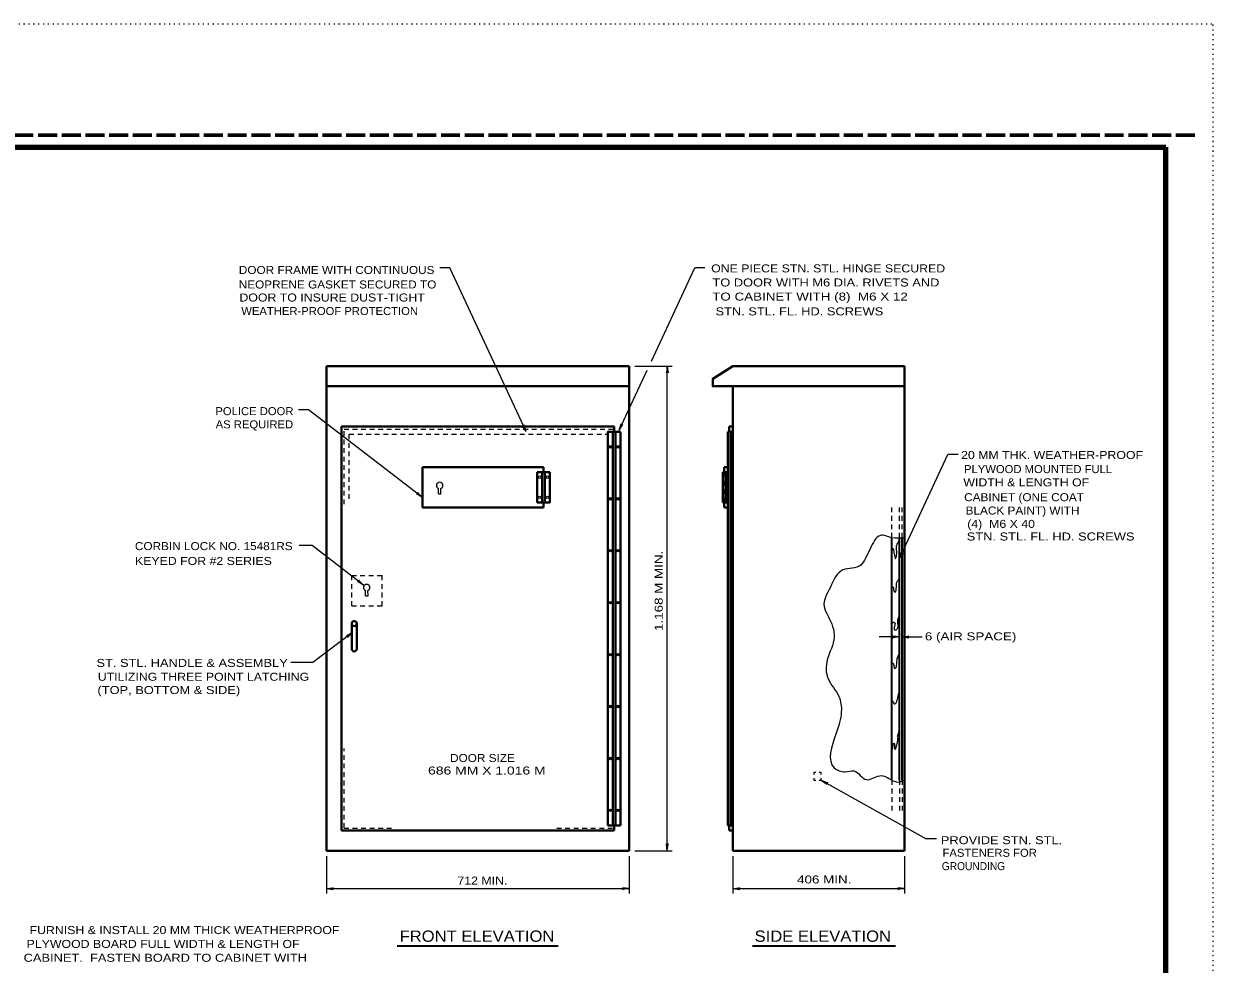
# Model space of a CAD drawing. Extents: x 312583 to 312854, y 144419 to 144597.
# Drawn here: x 312740.6 to 312853.5, y 144507.5 to 144596.8 of the extents above; entities that cross this region are included whole.
import ezdxf
from ezdxf.enums import TextEntityAlignment as Align

# ---------------------------------------------------------------- set-up
doc = ezdxf.new("R2010")
doc.units = 0
doc.header["$LTSCALE"] = 0.3
doc.header["$PDMODE"] = 32
doc.header["$PDSIZE"] = 0.15
for name, pattern in [('DOTTED', [1.5, 0.3, -1.2]), ('LONG_DASHED', [7.5, 6, -1.5]), ('SHORT_DASHED', [2.7, 1.5, -1.2])]:
    doc.linetypes.add(name, pattern=pattern)
for name, color, linetype, lineweight in [('1', 7, 'Continuous', 25), ('2', 7, 'Continuous', 13), ('63', 7, 'DOTTED', 13)]:
    doc.layers.add(name, color=color, linetype=linetype, lineweight=lineweight)

msp = doc.modelspace()

# ---------------------------------------------------------------- linework, layer by layer
at = {"layer": '1', "linetype": 'LONG_DASHED', "lineweight": 60}
msp.add_line((312851.75, 144586.2246), (312583.526, 144586.2246), dxfattribs=at)
at = {"layer": '1', "lineweight": 158}
msp.add_line((312849, 144423.1446), (312849, 144585.0846), dxfattribs=at)
at = {"layer": '1', "lineweight": 106}
msp.add_line((312849, 144423.1446), (312849, 144584.0756), dxfattribs=at)
at = {"layer": '1', "lineweight": 40}
for p, q in [((312769.3243, 144518.2993), (312769.3243, 144564.2993)), ((312769.3243, 144564.2993), (312798.0743, 144564.2993)), ((312798.0743, 144564.2993), (312798.0743, 144518.2993)), ((312824.2023, 144564.2993), (312807.9107, 144564.2993)), ((312824.2023, 144564.2993), (312824.2023, 144518.2993)), ((312769.3243, 144562.3827), (312798.0743, 144562.3827)), ((312807.9107, 144562.3827), (312807.9107, 144518.2993)), ((312796.518, 144520.6913), (312796.518, 144558.0663)), ((312796.6407, 144558.0663), (312796.6407, 144558.5493)), ((312796.7633, 144520.6913), (312796.7633, 144558.0663)), ((312797.2387, 144520.6913), (312797.2387, 144558.0663)), ((312807.4353, 144558.0663), (312807.4353, 144520.6913)), ((312807.9107, 144558.0663), (312807.4353, 144558.0663)), ((312807.9107, 144558.5493), (312807.5503, 144558.5493)), ((312807.5503, 144558.0663), (312807.5503, 144558.5493)), ((312807.673, 144558.0663), (312807.673, 144520.6913)), ((312778.4323, 144554.716), (312789.9323, 144554.716)), ((312778.4323, 144550.8827), (312778.4323, 144554.716)), ((312789.9323, 144554.233), (312789.9323, 144554.716)), ((312807.4353, 144554.716), (312807.075, 144554.716)), ((312807.075, 144554.716), (312807.075, 144554.233)), ((312789.3343, 144554.233), (312790.5303, 144554.233)), ((312789.3343, 144551.358), (312789.3343, 144554.233)), ((312789.8097, 144551.358), (312789.8097, 144554.233)), ((312790.055, 144551.358), (312790.055, 144554.233)), ((312806.9523, 144554.233), (312806.9523, 144551.358)), ((312806.9523, 144554.233), (312807.4353, 144554.233)), ((312807.1977, 144554.233), (312807.1977, 144551.358)), ((312789.9323, 144550.8827), (312789.9323, 144551.358)), ((312806.9523, 144551.358), (312807.4353, 144551.358)), ((312807.075, 144551.358), (312807.075, 144550.8827)), ((312778.4323, 144550.8827), (312789.9323, 144550.8827)), ((312807.4353, 144550.8827), (312807.075, 144550.8827)), ((312771.724, 144537.466), (312771.724, 144539.858)), ((312772.1993, 144537.466), (312772.1993, 144539.858)), ((312796.0427, 144520.6913), (312797.2387, 144520.6913)), ((312796.6407, 144520.216), (312796.6407, 144520.6913)), ((312807.4353, 144520.6913), (312807.9107, 144520.6913)), ((312807.5503, 144520.216), (312807.5503, 144520.6913)), ((312770.7657, 144520.216), (312796.6407, 144520.216)), ((312807.5503, 144520.216), (312807.9107, 144520.216)), ((312769.3243, 144518.2993), (312798.0743, 144518.2993)), ((312807.9107, 144518.2993), (312824.2023, 144518.2993))]:
    msp.add_line(p, q, dxfattribs=at)
at = {"layer": '1', "linetype": 'SHORT_DASHED'}
for p, q in [((312771.0033, 144558.3117), (312796.518, 144558.3117)), ((312771.0033, 144551.197), (312771.0033, 144558.3117)), ((312771.4863, 144557.8287), (312796.0427, 144557.8287)), ((312771.4863, 144551.6877), (312771.4863, 144557.8287)), ((312807.075, 144554.233), (312807.075, 144551.358)), ((312823.0063, 144548.0077), (312823.0063, 144550.8827)), ((312823.727, 144548.0077), (312823.727, 144550.8827)), ((312823.9647, 144548.0077), (312823.9647, 144550.8827)), ((312771.0033, 144520.4537), (312771.0033, 144528.0207)), ((312823.0063, 144525.0077), (312823.0063, 144522.1327)), ((312823.727, 144525.0077), (312823.727, 144522.1327)), ((312823.9647, 144525.0077), (312823.9647, 144522.1327)), ((312771.0033, 144520.4537), (312775.588, 144520.4537)), ((312791.182, 144520.4537), (312796.518, 144520.4537))]:
    msp.add_line(p, q, dxfattribs=at)
at = {"layer": '1'}
for p, q in [((312779.958, 144552.163), (312779.9657, 144552.6767)), ((312780.1957, 144552.163), (312780.188, 144552.6767)), ((312779.958, 144552.163), (312780.1957, 144552.163)), ((312773.0273, 144542.48), (312773.035, 144542.9937)), ((312773.0273, 144542.48), (312773.2727, 144542.48)), ((312773.2727, 144542.48), (312773.265, 144542.9937)), ((312816.298, 144525.7283), (312816.1063, 144525.7283)), ((312816.298, 144525.529), (312816.298, 144525.7283))]:
    msp.add_line(p, q, dxfattribs=at)
at = {"layer": '1', "lineweight": 35}
for p, q in [((312823.0063, 144525.0077), (312823.0063, 144548.0077)), ((312823.727, 144525.0077), (312823.727, 144548.0077)), ((312823.9647, 144525.0077), (312823.9647, 144548.0077))]:
    msp.add_line(p, q, dxfattribs=at)
at = {"layer": '1', "lineweight": 158}
msp.add_lwpolyline([(312616.5, 144423.1446), (312616.5, 144585.0846), (312849, 144585.0846)], dxfattribs=at)
at = {"layer": '1', "lineweight": 40}
for points in [[(312824.2023, 144562.3827), (312805.994, 144562.3827), (312805.994, 144563.1033), (312807.9107, 144564.2993)], [(312770.7657, 144520.216), (312770.7657, 144558.5493), (312796.6407, 144558.5493)], [(312796.0427, 144520.6913), (312796.0427, 144558.0663), (312797.2387, 144558.0663)], [(312789.3343, 144551.358), (312790.5303, 144551.358), (312790.5303, 144554.233)]]:
    msp.add_lwpolyline(points, dxfattribs=at)
at = {"layer": '1', "linetype": 'SHORT_DASHED'}
for points in [[(312771.724, 144541.537), (312771.724, 144544.412), (312774.599, 144544.412)], [(312771.724, 144541.537), (312774.599, 144541.537), (312774.599, 144544.412)]]:
    msp.add_lwpolyline(points, dxfattribs=at)
at = {"layer": '1'}
for points in [[(312815.7767, 144525.7283), (312815.5773, 144525.7283), (312815.5773, 144525.529)], [(312815.5773, 144525.1993), (312815.5773, 144525.0077), (312815.769, 144525.0077)], [(312816.1063, 144525.0077), (312816.298, 144525.0077), (312816.298, 144525.1993)]]:
    msp.add_lwpolyline(points, dxfattribs=at)
for centre in [(312796.2803, 144556.6308), (312796.9991, 144556.6308), (312789.572, 144553.7567), (312790.2907, 144553.7567), (312789.572, 144551.84), (312790.2907, 144551.84), (312796.2803, 144551.703), (312796.9991, 144551.703), (312796.2803, 144546.7743), (312796.9991, 144546.7743), (312796.2803, 144541.8456), (312796.9991, 144541.8456), (312796.2803, 144536.9169), (312796.9991, 144536.9169), (312796.2803, 144531.9882), (312796.9991, 144531.9882), (312796.2803, 144527.0595), (312796.9991, 144527.0595), (312796.2803, 144522.1317), (312796.9991, 144522.1317)]:
    msp.add_circle(centre, 0.1198, dxfattribs=at)
at = {"layer": '1', "lineweight": 40}
msp.add_circle((312771.9626, 144539.8609), 0.2396, dxfattribs=at)
at = {"layer": '1'}
for centre in [(312780.0768, 144552.9632), (312773.149, 144543.2773)]:
    msp.add_arc(centre, 0.3047, 291.97661, 248.03135, dxfattribs=at)
at = {"layer": '1', "lineweight": 40}
msp.add_arc((312771.9626, 144537.465), 0.2396, 180, 0, dxfattribs=at)
at = {"layer": '1'}
msp.add_spline([(312824.2023, 144548.0077), (312823.0063, 144548.0077), (312821.91, 144548.23), (312820.944, 144546.965), (312820.4993, 144546.0757), (312820.0547, 144545.4087), (312818.345, 144544.9563), (312817.1567, 144543.3233), (312816.5663, 144541.468), (312816.9343, 144540.5787), (312817.5323, 144538.57), (312816.8653, 144536.4157), (312816.9343, 144534.637), (312817.977, 144532.9273), (312818.1993, 144531.5167), (312817.678, 144529.3623), (312817.5323, 144526.1653), (312818.5673, 144525.7973), (312819.3877, 144525.874), (312820.576, 144525.0537), (312821.841, 144525.4217), (312823.0063, 144525.0077), (312823.3973, 144524.8313), (312824.2023, 144525.0077)], degree=3, dxfattribs=at)
at = {"layer": '1', "lineweight": 13}
for points in [[(312823.014, 144546.6583), (312823.0447, 144546.827), (312823.129, 144546.988), (312823.1673, 144546.873), (312823.198, 144546.6047), (312823.2823, 144546.183), (312823.3207, 144546.022), (312823.451, 144546.3287), (312823.4663, 144546.7197), (312823.428, 144547.1567), (312823.5507, 144547.4863), (312823.704, 144547.793)], [(312822.9987, 144543.1853), (312823.0447, 144543.3233), (312823.083, 144543.3463), (312823.152, 144543.285), (312823.152, 144543.1087), (312823.2287, 144542.917), (312823.2747, 144542.848), (312823.4203, 144543.1547), (312823.428, 144543.377), (312823.4433, 144543.6683), (312823.543, 144543.906), (312823.635, 144544.0133), (312823.727, 144544.228)], [(312822.9833, 144539.697), (312823.06, 144539.8887), (312823.1213, 144540.019), (312823.267, 144539.9423), (312823.2363, 144539.5973), (312823.3053, 144539.2293), (312823.497, 144539.3673), (312823.5813, 144539.812), (312823.5583, 144540.2183), (312823.6963, 144540.5633)], [(312823.014, 144535.9403), (312823.0523, 144536.0783), (312823.0677, 144536.109), (312823.1597, 144536.017), (312823.198, 144535.8407), (312823.221, 144535.672), (312823.2747, 144535.5877), (312823.3973, 144535.7027), (312823.451, 144535.8637), (312823.474, 144536.1703), (312823.4893, 144536.4233), (312823.5507, 144536.6457), (312823.6043, 144536.7683), (312823.6963, 144537.1133)], [(312823.014, 144532.429), (312823.0217, 144532.475), (312823.06, 144532.5057), (312823.1213, 144532.452), (312823.1597, 144532.3523), (312823.2287, 144532.2373), (312823.3513, 144532.2757), (312823.4587, 144532.4903), (312823.52, 144532.705), (312823.5737, 144532.8813), (312823.6197, 144533.142), (312823.6733, 144533.303), (312823.727, 144533.418)], [(312823.0063, 144527.7753), (312823.0293, 144527.875), (312823.0677, 144528.0207), (312823.0907, 144528.1203), (312823.106, 144528.289), (312823.1597, 144528.473), (312823.198, 144528.5037), (312823.2363, 144528.4347), (312823.244, 144528.2507), (312823.244, 144528.1203), (312823.2593, 144528.0053), (312823.2977, 144527.944), (312823.3207, 144527.9287), (312823.359, 144527.967), (312823.3973, 144528.0667), (312823.4357, 144528.2507), (312823.5047, 144528.473), (312823.566, 144528.8717), (312823.5813, 144529.0403), (312823.566, 144529.232), (312823.6197, 144529.4467), (312823.704, 144529.7687)]]:
    msp.add_spline(points, degree=3, dxfattribs=at)
at = {"layer": '1'}
for p in [(312796.2803, 144556.6327), (312797.001, 144556.6327), (312796.2803, 144551.703), (312797.001, 144551.703), (312796.2803, 144546.7733), (312797.001, 144546.7733), (312796.2803, 144541.8437), (312797.001, 144541.8437), (312796.2803, 144536.914), (312797.001, 144536.914), (312796.2803, 144531.9843), (312797.001, 144531.9843), (312796.2803, 144527.0623), (312797.001, 144527.0623), (312796.2803, 144522.1327), (312797.001, 144522.1327)]:
    msp.add_point(p, dxfattribs=at)
at = {"layer": '2'}
for p, q in [((312800.1673, 144564.767), (312804.2843, 144573.6143)), ((312805.2427, 144573.6143), (312804.2843, 144573.6143)), ((312797.1083, 144558.2043), (312799.761, 144563.9007)), ((312798.6033, 144564.2993), (312802.153, 144564.2993)), ((312801.67, 144564.2993), (312801.5933, 144563.6477)), ((312801.5933, 144563.6477), (312801.67, 144563.8547)), ((312801.67, 144518.2993), (312801.67, 144564.2993)), ((312801.67, 144564.2993), (312801.7543, 144563.6477)), ((312801.7543, 144563.6477), (312801.67, 144563.8547)), ((312767.63, 144560.1517), (312766.664, 144560.1517)), ((312778.4323, 144551.841), (312767.63, 144560.1517)), ((312787.9237, 144558.6413), (312788.0847, 144558.488)), ((312788.2763, 144558.0893), (312787.9237, 144558.6413)), ((312788.0693, 144558.7103), (312788.0847, 144558.488)), ((312788.2763, 144558.0893), (312788.0693, 144558.7103)), ((312797.1083, 144558.2043), (312797.3153, 144558.833)), ((312797.1083, 144558.2043), (312797.461, 144558.764)), ((312797.3153, 144558.833), (312797.3, 144558.6107)), ((312797.461, 144558.764), (312797.3, 144558.6107)), ((312823.727, 144546.022), (312828.3193, 144555.8967)), ((312829.2777, 144555.8967), (312828.3193, 144555.8967)), ((312777.9647, 144552.301), (312778.0797, 144552.1093)), ((312778.4323, 144551.841), (312777.9647, 144552.301)), ((312777.865, 144552.1707), (312778.0797, 144552.1093)), ((312778.4323, 144551.841), (312777.865, 144552.1707)), ((312767.9673, 144547.264), (312766.7483, 144547.264)), ((312772.8357, 144543.515), (312767.9673, 144547.264)), ((312823.727, 144546.022), (312823.9263, 144546.643)), ((312823.9263, 144546.643), (312823.911, 144546.4207)), ((312823.727, 144546.022), (312824.072, 144546.574)), ((312824.072, 144546.574), (312823.911, 144546.4207)), ((312772.2683, 144543.8523), (312772.483, 144543.791)), ((312772.8357, 144543.515), (312772.2683, 144543.8523)), ((312772.368, 144543.975), (312772.483, 144543.791)), ((312772.8357, 144543.515), (312772.368, 144543.975)), ((312771.793, 144539.007), (312768.0363, 144536.1627)), ((312771.793, 144539.007), (312771.2257, 144538.6773)), ((312771.2257, 144538.6773), (312771.4403, 144538.7387)), ((312771.793, 144539.007), (312771.3253, 144538.5547)), ((312771.3253, 144538.5547), (312771.4403, 144538.7387)), ((312823.727, 144538.593), (312821.8027, 144538.593)), ((312823.0753, 144538.6697), (312823.2823, 144538.593)), ((312823.727, 144538.593), (312823.0753, 144538.6697)), ((312823.0753, 144538.5087), (312823.2823, 144538.593)), ((312823.727, 144538.593), (312823.0753, 144538.5087)), ((312823.9647, 144538.593), (312824.6163, 144538.6697)), ((312823.9647, 144538.593), (312825.8813, 144538.593)), ((312823.9647, 144538.593), (312824.6163, 144538.5087)), ((312824.6163, 144538.6697), (312824.4093, 144538.593)), ((312824.6163, 144538.5087), (312824.4093, 144538.593)), ((312768.0363, 144536.1627), (312765.9587, 144536.1627)), ((312816.298, 144525.0077), (312826.2647, 144519.4187)), ((312816.298, 144525.0077), (312816.827, 144524.6167)), ((312816.298, 144525.0077), (312816.9037, 144524.7623)), ((312816.827, 144524.6167), (312816.6813, 144524.793)), ((312816.9037, 144524.7623), (312816.6813, 144524.793)), ((312801.5933, 144518.951), (312801.67, 144518.744)), ((312801.67, 144518.2993), (312801.5933, 144518.951)), ((312801.7543, 144518.951), (312801.67, 144518.744)), ((312801.67, 144518.2993), (312801.7543, 144518.951)), ((312827.223, 144519.4187), (312826.2647, 144519.4187)), ((312769.3243, 144517.778), (312769.3243, 144514.2283)), ((312798.0743, 144517.778), (312798.0743, 144514.2283)), ((312798.6033, 144518.2993), (312802.153, 144518.2993)), ((312807.9107, 144517.778), (312807.9107, 144514.2283)), ((312824.2023, 144517.778), (312824.2023, 144514.2283)), ((312769.3243, 144514.7037), (312769.976, 144514.788)), ((312769.3243, 144514.7037), (312798.0743, 144514.7037)), ((312769.3243, 144514.7037), (312769.976, 144514.627)), ((312769.976, 144514.788), (312769.769, 144514.7037)), ((312769.976, 144514.627), (312769.769, 144514.7037)), ((312797.4303, 144514.788), (312797.6373, 144514.7037)), ((312798.0743, 144514.7037), (312797.4303, 144514.788)), ((312797.4303, 144514.627), (312797.6373, 144514.7037)), ((312798.0743, 144514.7037), (312797.4303, 144514.627)), ((312807.9107, 144514.7037), (312808.5623, 144514.788)), ((312807.9107, 144514.7037), (312824.2023, 144514.7037)), ((312807.9107, 144514.7037), (312808.5623, 144514.627)), ((312808.5623, 144514.788), (312808.3553, 144514.7037)), ((312808.5623, 144514.627), (312808.3553, 144514.7037)), ((312823.5583, 144514.788), (312823.7653, 144514.7037)), ((312824.2023, 144514.7037), (312823.5583, 144514.788)), ((312823.5583, 144514.627), (312823.7653, 144514.7037)), ((312824.2023, 144514.7037), (312823.5583, 144514.627))]:
    msp.add_line(p, q, dxfattribs=at)
at = {"layer": '2', "lineweight": 35}
for p, q in [((312776.0474, 144509.2833), (312791.3211, 144509.2833)), ((312809.7603, 144509.2833), (312823.3524, 144509.2833))]:
    msp.add_line(p, q, dxfattribs=at)
at = {"layer": '2'}
msp.add_lwpolyline([(312788.2763, 144558.0893), (312781.0467, 144573.6143), (312780.0883, 144573.6143)], dxfattribs=at)
at = {"layer": '63'}
msp.add_line((312601.2, 144596.7846), (312853.5, 144596.7846), dxfattribs=at)
msp.add_lwpolyline([(312601.2, 144418.5846), (312853.5, 144418.5846), (312853.5, 144596.7846)], dxfattribs=at)

# ---------------------------------------------------------------- texts
at = {"layer": '2'}
for s, height, width, p in [('DOOR FRAME WITH CONTINUOUS', 0.76, 1.1, (312770.293, 144573.0418)), ('ONE PIECE STN. STL. HINGE SECURED', 0.76, 1.15, (312816.9498, 144573.1898)), ('TO DOOR WITH M6 DIA. RIVETS AND', 0.76, 1.2, (312816.7357, 144571.8528)), ('NEOPRENE GASKET SECURED TO', 0.76, 1.1, (312770.3787, 144571.6641)), ('DOOR TO INSURE DUST-TIGHT', 0.76, 1.15, (312769.8622, 144570.4268)), ('TO CABINET WITH (8)  M6 X 12 ', 0.76, 1.25, (312815.403, 144570.5157)), ('WEATHER-PROOF PROTECTION', 0.76, 1.05, (312769.6301, 144569.1435)), ('STN. STL. FL. HD. SCREWS', 0.76, 1.2, (312814.2174, 144569.1086)), ('POLICE DOOR', 0.76, 1.05, (312762.4875, 144559.6416)), ('AS REQUIRED', 0.76, 1.05, (312762.4863, 144558.3877)), ('20 MM THK. WEATHER-PROOF', 0.76, 1.15, (312838.2045, 144555.4799)), ('PLYWOOD MOUNTED FULL', 0.76, 1.05, (312836.8732, 144554.1428)), ('WIDTH & LENGTH OF', 0.76, 1.15, (312835.7522, 144552.8836)), ('CABINET (ONE COAT', 0.76, 1.1, (312835.542, 144551.4764)), ('BLACK PAINT) WITH', 0.76, 1.1, (312835.4019, 144550.2096)), ('(4)  M6 X 40', 0.76, 1.15, (312833.3637, 144548.9427)), ('STN. STL. FL. HD. SCREWS', 0.76, 1.2, (312838.0641, 144547.746)), ('CORBIN LOCK NO. 15481RS', 0.76, 1.1, (312758.6315, 144546.8341)), ('KEYED FOR #2 SERIES', 0.76, 1.15, (312757.6453, 144545.4246)), (' 6 (AIR SPACE)', 0.76, 1.25, (312830.295, 144538.2693)), ('ST. STL. HANDLE & ASSEMBLY', 0.76, 1.2, (312756.5746, 144535.7481)), ('UTILIZING THREE POINT LATCHING', 0.76, 1.15, (312757.6525, 144534.4341)), ('(TOP, BOTTOM & SIDE)', 0.76, 1.2, (312754.3609, 144533.1737)), ('DOOR SIZE', 0.76, 1.1, (312784.1355, 144526.724)), ('686 MM X 1.016 M', 0.76, 1.3, (312784.5491, 144525.5338)), ('PROVIDE STN. STL.', 0.76, 1.2, (312833.4051, 144518.924)), ('FASTENERS FOR', 0.76, 1.05, (312832.2841, 144517.7272)), ('GROUNDING', 0.76, 0.95, (312830.7429, 144516.4604)), ('712 MIN.', 0.76, 1.15, (312784.1313, 144515.0906)), ('406 MIN.', 0.76, 1.25, (312816.5784, 144515.196)), ('FURNISH & INSTALL 20 MM THICK WEATHERPROOF', 0.76, 1.15, (312755.8508, 144510.392)), ('FRONT ELEVATION', 1.07, 1.1, (312783.6153, 144509.6611)), ('SIDE ELEVATION', 1.07, 1.1, (312816.4396, 144509.6611)), ('PLYWOOD BOARD FULL WIDTH & LENGTH OF', 0.76, 1.15, (312753.8189, 144509.0779)), ('CABINET.  FASTEN BOARD TO CABINET WITH', 0.76, 1.2, (312754.0292, 144507.764))]:
    msp.add_text(s, height=height, dxfattribs=dict(at, width=width)).set_placement(p, align=Align.CENTER)
at = {"layer": '2', "width": 1.25}
msp.add_text('1.168 M MIN.', height=0.76, rotation=90, dxfattribs=at).set_placement((312801.2462, 144542.9665), align=Align.CENTER)

doc.saveas('drawing.dxf')
